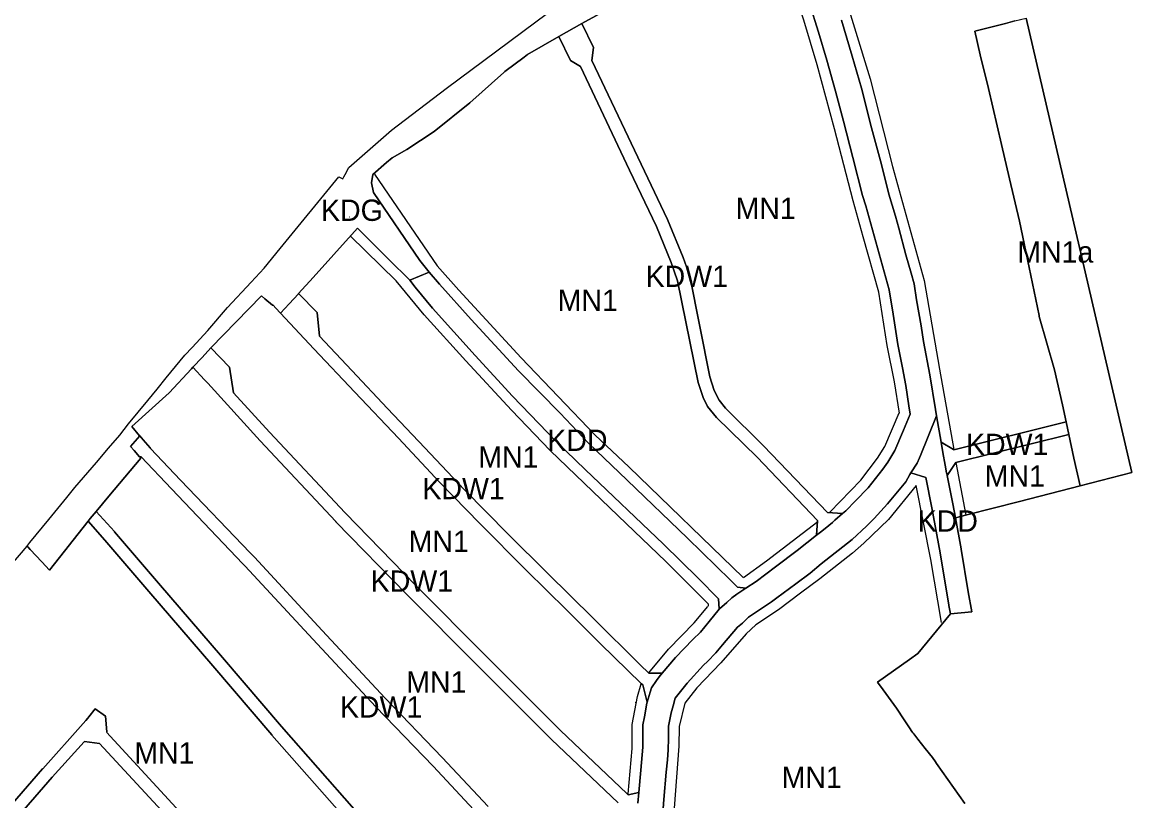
# Model space of a CAD drawing. Extents: x -284239 to -281592, y 34477 to 37267.
# Drawn here: x -283616 to -283093, y 35969 to 36334 of the extents above; entities that cross this region are included whole.
import ezdxf

# ---------------------------------------------------------------- set-up
doc = ezdxf.new("R2010")
doc.units = 0
for name, color, linetype in [('linie_rozgraniczajace', 7, 'Continuous'), ('linie_zabudowy_nieprzekraczalne', 7, 'Continuous'), ('oznaczenia_przeznaczen', 7, 'Continuous')]:
    doc.layers.add(name, color=color, linetype=linetype)

msp = doc.modelspace()

# ---------------------------------------------------------------- linework, layer by layer
at = {"layer": 'linie_rozgraniczajace'}
for points in [[(-283613.963, 36088.161), (-283613.66, 36088.52), (-283612.644, 36089.761), (-283603.69, 36100.7), (-283595.29, 36110.98), (-283591.49, 36115.62), (-283581.32, 36127.44), (-283575.7, 36134.13), (-283570.52, 36140.31), (-283566.39, 36145.49), (-283557.34, 36156.49), (-283552.95, 36161.85), (-283548.66, 36167.08), (-283539.89, 36177.82), (-283536.52, 36181.44), (-283529.1, 36189.39), (-283519.93, 36200.12), (-283508.754, 36212.115), (-283502.73, 36218.58), (-283495.149, 36227.855), (-283467.65, 36261.5), (-283466.676, 36261.042), (-283465.78, 36260.62), (-283465.27, 36261.48), (-283464.672, 36262.697), (-283463.07, 36265.96), (-283442.91, 36283.51), (-283417.32, 36302.99), (-283363.72, 36342.94)], [(-283246.84, 36343.001), (-283242.619, 36329.4), (-283238.711, 36316.321), (-283234.699, 36301.782), (-283230.895, 36287.661), (-283226.465, 36270.621), (-283221.984, 36252.696), (-283220.473, 36247.954), (-283209.478, 36208.403), (-283207.55, 36196.991), (-283205.361, 36182.818), (-283203.225, 36171.927), (-283201.661, 36163.485), (-283200.202, 36154.002), (-283199.552, 36150.099), (-283202.756, 36142.589), (-283206.82, 36133.002), (-283210.155, 36127.478), (-283212.396, 36124.195), (-283219.378, 36115.441), (-283225.215, 36109.396), (-283229.852, 36104.758), (-283231.322, 36103.46), (-283238.474, 36103.931), (-283268.495, 36135.283), (-283286.222, 36152.944), (-283289.265, 36156.648), (-283291.514, 36161.146), (-283293.631, 36167.628), (-283303.023, 36214.857), (-283306.198, 36223.72), (-283313.474, 36241.58), (-283348.995, 36316.183), (-283348.238, 36322.21), (-283353.632, 36333.486), (-283340.515, 36340.672)], [(-283207.55, 36196.991), (-283209.478, 36208.403), (-283220.473, 36247.954), (-283221.984, 36252.696), (-283226.465, 36270.621), (-283230.895, 36287.661), (-283234.699, 36301.782), (-283238.711, 36316.321), (-283242.619, 36329.4), (-283246.84, 36343.001)], [(-283340.515, 36340.672), (-283353.632, 36333.486), (-283364.544, 36327.384), (-283379.163, 36319.001), (-283380.781, 36317.801), (-283389.817, 36311.033), (-283390.333, 36310.51), (-283406.261, 36296.276), (-283423.036, 36282.89), (-283435.745, 36274.418), (-283442.674, 36270.514), (-283445.279, 36268.201), (-283451.741, 36262.623), (-283452.351, 36258.659), (-283451.504, 36254.253), (-283429.645, 36222.228), (-283425.239, 36216.805), (-283434.389, 36213.078), (-283436.183, 36214.833), (-283442.354, 36220.872), (-283458.959, 36237.478), (-283481.206, 36212.682), (-283483.36, 36210.282), (-283486.6, 36206.713), (-283486.665, 36206.641), (-283490.985, 36201.882), (-283494.997, 36197.453), (-283497.179, 36199.791), (-283498.58, 36201.281), (-283498.852, 36201.283), (-283502.383, 36204.239), (-283504.055, 36205.639), (-283527.673, 36181.245), (-283527.679, 36181.238)], [(-283231.833, 36335.08), (-283226.882, 36318.249), (-283222.453, 36303.19), (-283217.815, 36284.587), (-283213.594, 36269.006), (-283211.562, 36261.033), (-283209.582, 36253.425), (-283206.56, 36243.108), (-283204.944, 36237.428), (-283201.609, 36224.922), (-283199.212, 36216.272), (-283197.805, 36211.217), (-283196.659, 36203.818), (-283194.47, 36191.52), (-283193.376, 36184.172), (-283190.458, 36168.54), (-283187.696, 36152.23), (-283187.279, 36149.312), (-283194.803, 36130.699), (-283195.252, 36129.667), (-283196.398, 36127.061), (-283199.252, 36122.513), (-283199.733, 36121.746), (-283201.661, 36118.359), (-283210.207, 36107.937), (-283216.46, 36101.163), (-283220.108, 36097.515), (-283226.83, 36091.21), (-283241.316, 36079.746), (-283246.579, 36075.421), (-283253.249, 36070.419), (-283262.108, 36063.853), (-283264.609, 36061.977), (-283275.396, 36054.734), (-283278.314, 36052.024), (-283280.607, 36050.044), (-283287.641, 36041.759), (-283290.872, 36038.007), (-283294.728, 36033.942), (-283296.552, 36032.223), (-283304.264, 36023.781), (-283309.892, 36016.799), (-283310.882, 36013.099), (-283311.82, 36009.868), (-283313.07, 36003.615), (-283313.07, 35997.779), (-283313.227, 35992.411), (-283313.539, 35987.826), (-283314.113, 35981.938), (-283315.155, 35969.119), (-283316.458, 35952.079)], [(-283150.436, 36334.741), (-283154.879, 36333.612), (-283169.349, 36329.955), (-283166.705, 36318.833), (-283162.936, 36302.976), (-283156.734, 36276.738), (-283152.971, 36260.572), (-283148.359, 36240.695), (-283143.854, 36219.017), (-283139.137, 36196.384), (-283139.029, 36196.009), (-283131.834, 36170.915), (-283128.218, 36154.405), (-283126.492, 36146.51), (-283179.126, 36133.403), (-283179.331, 36133.563), (-283185.081, 36136.952), (-283187.279, 36149.312), (-283187.696, 36152.23), (-283190.458, 36168.54), (-283193.376, 36184.172), (-283194.47, 36191.52), (-283196.659, 36203.818), (-283197.805, 36211.217), (-283199.212, 36216.272), (-283201.609, 36224.922), (-283204.944, 36237.428), (-283206.56, 36243.108), (-283209.582, 36253.425), (-283211.562, 36261.033), (-283213.594, 36269.006), (-283217.815, 36284.587), (-283222.453, 36303.19), (-283226.882, 36318.249), (-283231.833, 36335.08)], [(-283173.975, 35967.24), (-283187.253, 35986.027), (-283187.803, 35986.836), (-283189.19, 35988.86), (-283192.547, 35993.138), (-283195.962, 35997.492), (-283197.93, 36000), (-283198.293, 36000.505), (-283198.766, 36001.163), (-283200, 36002.88), (-283202.432, 36006.641), (-283206.066, 36012.004), (-283212.292, 36020.669), (-283214.88, 36024.27), (-283199.925, 36034.933), (-283195.96, 36037.76), (-283180.69, 36056.377), (-283170.709, 36057.35), (-283172.447, 36066.68), (-283172.396, 36066.745), (-283175.668, 36086.704), (-283175.681, 36086.749), (-283175.687, 36086.809), (-283178.408, 36101.439), (-283172.953, 36102.779), (-283148.359, 36109.139), (-283119.79, 36116.401), (-283095.587, 36122.661), (-283145.114, 36336.093)], [(-283327.42, 35967.384), (-283326.952, 35972.467), (-283325.993, 35982.875), (-283325.108, 35993.662), (-283325.003, 36004.188), (-283324.326, 36007.992), (-283323.18, 36014.453), (-283323.073, 36014.805), (-283321.611, 36019.608), (-283320.991, 36021.644), (-283318.643, 36025.013), (-283317.396, 36026.803), (-283316.022, 36028.44), (-283309.788, 36035.87), (-283301.659, 36044.312), (-283298.063, 36047.803), (-283293.999, 36052.701), (-283289.232, 36058.583), (-283289.1, 36058.746), (-283285.654, 36061.727), (-283283.368, 36063.853), (-283280.969, 36065.555), (-283276.672, 36068.404), (-283271.904, 36071.565), (-283262.733, 36078.339), (-283252.624, 36086.051), (-283243.565, 36093.203), (-283241.733, 36094.649), (-283239.569, 36096.412), (-283236.106, 36099.235), (-283234.957, 36100.249), (-283231.322, 36103.46), (-283229.852, 36104.758), (-283225.215, 36109.396), (-283219.378, 36115.441), (-283212.396, 36124.195), (-283210.155, 36127.478), (-283206.82, 36133.002), (-283202.756, 36142.589), (-283199.552, 36150.099), (-283200.202, 36154.002), (-283201.661, 36163.485), (-283203.225, 36171.927), (-283205.361, 36182.818), (-283207.55, 36196.991)], [(-283527.679, 36181.238), (-283531.867, 36176.727), (-283536.178, 36172.086), (-283536.792, 36171.422), (-283547.242, 36160.125), (-283564.864, 36144.367), (-283561.188, 36139.938), (-283561.136, 36139.876), (-283565.373, 36134.962), (-283563.695, 36132.984), (-283561.208, 36130.053), (-283560.628, 36129.37), (-283575.54, 36111.578), (-283581.519, 36104.45), (-283584.351, 36101.073), (-283585.361, 36099.794), (-283603.498, 36076.841), (-283607.105, 36080.742), (-283612.5, 36086.577), (-283613.691, 36087.866), (-283613.963, 36088.161)], [(-283336.674, 35967.549), (-283367.894, 35997.315), (-283367.914, 35997.344), (-283367.946, 35997.365), (-283402.674, 36032.094), (-283435.824, 36065.377), (-283469.112, 36099.589), (-283469.139, 36099.622), (-283504.663, 36137.523), (-283529.151, 36164.573), (-283530.67, 36166.25), (-283536.178, 36172.086), (-283531.867, 36176.727), (-283527.679, 36181.238), (-283527.673, 36181.245), (-283519.066, 36172.18), (-283517.135, 36160.132), (-283500.301, 36141.643), (-283464.792, 36103.753), (-283431.552, 36069.589), (-283398.427, 36036.332), (-283363.728, 36001.633), (-283332.57, 35971.927), (-283331.992, 35971.417), (-283326.952, 35972.467), (-283327.42, 35967.384)], [(-283397.628, 35965.812), (-283419.135, 35988.903), (-283419.159, 35988.932), (-283445.93, 36016.761), (-283475.478, 36048.557), (-283507.302, 36082.891), (-283507.325, 36082.919), (-283509.297, 36084.981), (-283541.91, 36119.091), (-283556.017, 36133.906), (-283556.017, 36134.178), (-283556.172, 36134.27), (-283559.524, 36138.085), (-283561.135, 36139.918), (-283561.188, 36139.938), (-283564.864, 36144.367), (-283547.242, 36160.125), (-283536.792, 36171.422), (-283536.178, 36172.086), (-283530.67, 36166.25), (-283529.151, 36164.573), (-283504.663, 36137.523), (-283469.139, 36099.622), (-283469.112, 36099.589), (-283435.824, 36065.377), (-283402.674, 36032.094), (-283367.946, 35997.365), (-283367.914, 35997.344), (-283367.894, 35997.315), (-283336.674, 35967.549)], [(-283402.356, 35962.085), (-283423.5, 35984.79), (-283450.272, 36012.62), (-283450.297, 36012.651), (-283479.876, 36044.475), (-283511.678, 36078.789), (-283512.696, 36079.854), (-283546.263, 36114.963), (-283560.489, 36130.12), (-283561.208, 36130.053), (-283563.695, 36132.984), (-283565.373, 36134.962), (-283561.136, 36139.876), (-283561.188, 36139.938), (-283561.135, 36139.918), (-283559.524, 36138.085), (-283556.172, 36134.27), (-283556.017, 36134.178), (-283556.017, 36133.906), (-283541.91, 36119.091), (-283509.297, 36084.981), (-283507.325, 36082.919), (-283507.302, 36082.891), (-283475.478, 36048.557), (-283445.93, 36016.761), (-283419.159, 35988.932), (-283419.135, 35988.903), (-283397.628, 35965.812)], [(-283460.545, 35964.685), (-283494.569, 36003.366), (-283522.268, 36035.835), (-283552.336, 36070.789), (-283572.972, 36094.874), (-283572.999, 36094.894), (-283573.024, 36094.934), (-283581.519, 36104.45), (-283575.54, 36111.578), (-283560.628, 36129.37), (-283561.208, 36130.053), (-283560.489, 36130.12), (-283546.263, 36114.963), (-283512.696, 36079.854), (-283511.678, 36078.789), (-283479.876, 36044.475), (-283450.297, 36012.651), (-283450.272, 36012.62), (-283423.5, 35984.79), (-283402.356, 35962.085)], [(-283316.458, 35952.079), (-283315.155, 35969.119), (-283314.113, 35981.938), (-283313.539, 35987.826), (-283313.227, 35992.411), (-283313.07, 35997.779), (-283313.07, 36003.615), (-283311.82, 36009.868), (-283310.882, 36013.099), (-283309.892, 36016.799), (-283304.264, 36023.781), (-283296.552, 36032.223), (-283294.728, 36033.942), (-283290.872, 36038.007), (-283287.641, 36041.759), (-283280.607, 36050.044), (-283278.314, 36052.024), (-283275.396, 36054.734), (-283264.609, 36061.977), (-283262.108, 36063.853), (-283253.249, 36070.419), (-283246.579, 36075.421), (-283241.316, 36079.746), (-283226.83, 36091.21), (-283220.108, 36097.515), (-283216.46, 36101.163), (-283210.207, 36107.937), (-283201.661, 36118.359), (-283199.733, 36121.746), (-283199.252, 36122.513), (-283192.281, 36120.369), (-283192.261, 36120.287), (-283189.442, 36106.075), (-283185.528, 36085.033), (-283181.494, 36060.432), (-283181.473, 36060.357), (-283181.464, 36060.265), (-283180.69, 36056.377), (-283195.96, 36037.76), (-283199.925, 36034.933), (-283214.88, 36024.27), (-283212.292, 36020.669), (-283206.066, 36012.004), (-283202.432, 36006.641), (-283200, 36002.88), (-283198.766, 36001.163), (-283198.293, 36000.505), (-283197.93, 36000), (-283195.962, 35997.492), (-283192.547, 35993.138), (-283189.19, 35988.86), (-283187.803, 35986.836), (-283187.253, 35986.027), (-283173.975, 35967.24)], [(-283465.066, 35960.742), (-283499.091, 35999.424), (-283499.119, 35999.455), (-283526.824, 36031.931), (-283556.888, 36066.881), (-283577.502, 36090.94), (-283585.361, 36099.794), (-283584.351, 36101.073), (-283581.519, 36104.45), (-283573.024, 36094.934), (-283572.999, 36094.894), (-283572.972, 36094.874), (-283552.336, 36070.789), (-283522.268, 36035.835), (-283494.569, 36003.366), (-283460.545, 35964.685)], [(-283625.65, 36074.31), (-283613.963, 36088.161), (-283613.691, 36087.866), (-283612.5, 36086.577), (-283607.105, 36080.742), (-283603.498, 36076.841), (-283585.361, 36099.794), (-283577.502, 36090.94), (-283556.888, 36066.881), (-283526.824, 36031.931), (-283499.119, 35999.455), (-283499.091, 35999.424), (-283465.066, 35960.742)], [(-283540.379, 35961.4), (-283576.638, 36000.7), (-283576.568, 36000.86), (-283577.114, 36008.231), (-283582.059, 36011.652), (-283584.95, 36008.003), (-283585.504, 36007.304), (-283586.354, 36006.232), (-283587.63, 36004.808), (-283606.651, 35983.587), (-283606.677, 35983.554), (-283625.75, 35961.486)], [(-283625.75, 35961.486), (-283606.677, 35983.554), (-283606.651, 35983.587), (-283587.63, 36004.808), (-283586.354, 36006.232), (-283585.504, 36007.304), (-283584.95, 36008.003), (-283582.059, 36011.652), (-283577.114, 36008.231), (-283576.568, 36000.86), (-283576.638, 36000.7), (-283540.379, 35961.4)], [(-283621.534, 35957.2), (-283602.166, 35979.602), (-283587.205, 35996.293), (-283587.058, 35996.351), (-283580.055, 35995.51), (-283548.885, 35961.766)], [(-283548.885, 35961.766), (-283580.055, 35995.51), (-283587.058, 35996.351), (-283587.205, 35996.293), (-283602.166, 35979.602), (-283621.534, 35957.2)]]:
    msp.add_lwpolyline(points, dxfattribs=at)
for points in [[(-283364.544, 36327.384), (-283353.632, 36333.486), (-283348.238, 36322.21), (-283348.995, 36316.183), (-283313.474, 36241.58), (-283306.198, 36223.72), (-283303.023, 36214.857), (-283293.631, 36167.628), (-283291.514, 36161.146), (-283289.265, 36156.648), (-283286.222, 36152.944), (-283268.495, 36135.283), (-283238.474, 36103.931), (-283231.322, 36103.46), (-283234.957, 36100.249), (-283236.106, 36099.235), (-283239.569, 36096.412), (-283241.733, 36094.649), (-283243.565, 36093.203), (-283243.095, 36099.961), (-283243.116, 36100.138), (-283271.406, 36129.859), (-283290.456, 36148.512), (-283294.689, 36153.738), (-283296.673, 36157.971), (-283299.055, 36164.917), (-283308.712, 36212.674), (-283311.755, 36221.339), (-283318.634, 36238.206), (-283331.334, 36264.731), (-283354.372, 36313.367), (-283359.03, 36316.166)], [(-283169.349, 36329.955), (-283154.879, 36333.612), (-283150.436, 36334.741), (-283145.155, 36336.082), (-283145.114, 36336.093), (-283095.587, 36122.661), (-283119.79, 36116.401), (-283122.758, 36129.44), (-283125.189, 36140.555), (-283126.492, 36146.51), (-283128.218, 36154.405), (-283131.834, 36170.915), (-283139.029, 36196.009), (-283139.137, 36196.384), (-283143.854, 36219.017), (-283148.359, 36240.695), (-283152.971, 36260.572), (-283156.734, 36276.738), (-283162.936, 36302.976), (-283166.705, 36318.833)], [(-283452.351, 36258.659), (-283451.741, 36262.623), (-283445.279, 36268.201), (-283442.674, 36270.514), (-283435.745, 36274.418), (-283423.036, 36282.89), (-283406.261, 36296.276), (-283390.333, 36310.51), (-283389.817, 36311.033), (-283380.781, 36317.801), (-283379.163, 36319.001), (-283364.544, 36327.384), (-283359.03, 36316.166), (-283354.372, 36313.367), (-283331.334, 36264.731), (-283318.634, 36238.206), (-283311.755, 36221.339), (-283308.712, 36212.674), (-283299.055, 36164.917), (-283296.673, 36157.971), (-283294.689, 36153.738), (-283290.456, 36148.512), (-283271.406, 36129.859), (-283243.116, 36100.138), (-283243.095, 36099.961), (-283243.565, 36093.203), (-283252.624, 36086.051), (-283262.733, 36078.339), (-283271.904, 36071.565), (-283276.672, 36068.404), (-283280.709, 36068.859), (-283283.887, 36072.182), (-283304.042, 36091.801), (-283332.345, 36119.031), (-283350.57, 36136.399), (-283363.863, 36150.55), (-283383.375, 36170.49), (-283405.674, 36194.505), (-283420.463, 36211.063), (-283425.239, 36216.805), (-283429.645, 36222.228), (-283451.504, 36254.253)], [(-283486.6, 36206.713), (-283483.36, 36210.282), (-283481.206, 36212.682), (-283458.959, 36237.478), (-283442.354, 36220.872), (-283436.183, 36214.833), (-283434.389, 36213.078), (-283431.865, 36209.652), (-283423.685, 36199.865), (-283403.744, 36177.566), (-283386.162, 36158.591), (-283365.579, 36137.149), (-283352.071, 36124.07), (-283315.406, 36089.12), (-283299.11, 36073.039), (-283289.62, 36063.367), (-283289.246, 36058.643), (-283289.232, 36058.583), (-283293.999, 36052.701), (-283298.063, 36047.803), (-283301.659, 36044.312), (-283309.788, 36035.87), (-283316.022, 36028.44), (-283322.252, 36028.507), (-283326.293, 36032.417), (-283348.412, 36054.233), (-283369.752, 36075.356), (-283388.228, 36093.702), (-283408.96, 36114.738), (-283427.35, 36134.299), (-283444.786, 36152.818), (-283461.614, 36170.558), (-283476.714, 36186.678), (-283477.857, 36197.778)], [(-283434.389, 36213.078), (-283425.239, 36216.805), (-283420.463, 36211.063), (-283405.674, 36194.505), (-283383.375, 36170.49), (-283363.863, 36150.55), (-283350.57, 36136.399), (-283332.345, 36119.031), (-283304.042, 36091.801), (-283283.887, 36072.182), (-283280.709, 36068.859), (-283276.672, 36068.404), (-283280.969, 36065.555), (-283283.368, 36063.853), (-283285.654, 36061.727), (-283289.1, 36058.746), (-283289.232, 36058.583), (-283289.246, 36058.643), (-283289.62, 36063.367), (-283299.11, 36073.039), (-283315.406, 36089.12), (-283352.071, 36124.07), (-283365.579, 36137.149), (-283386.162, 36158.591), (-283403.744, 36177.566), (-283423.685, 36199.865), (-283431.865, 36209.652)], [(-283527.673, 36181.245), (-283504.055, 36205.639), (-283502.383, 36204.239), (-283498.852, 36201.283), (-283498.58, 36201.281), (-283497.179, 36199.791), (-283494.997, 36197.453), (-283479.483, 36180.837), (-283460.139, 36160.409), (-283439.754, 36138.766), (-283420.324, 36117.99), (-283401.587, 36098.777), (-283379.727, 36076.787), (-283360.643, 36058.007), (-283345.029, 36042.436), (-283325.685, 36023.526), (-283325.076, 36022.94), (-283323.073, 36014.805), (-283323.18, 36014.453), (-283324.326, 36007.992), (-283325.003, 36004.188), (-283325.108, 35993.662), (-283325.993, 35982.875), (-283326.952, 35972.467), (-283331.992, 35971.417), (-283332.57, 35971.927), (-283363.728, 36001.633), (-283398.427, 36036.332), (-283431.552, 36069.589), (-283464.792, 36103.753), (-283500.301, 36141.643), (-283517.135, 36160.132), (-283519.066, 36172.18)], [(-283494.997, 36197.453), (-283490.985, 36201.882), (-283486.665, 36206.641), (-283486.6, 36206.713), (-283477.857, 36197.778), (-283476.714, 36186.678), (-283461.614, 36170.558), (-283444.786, 36152.818), (-283427.35, 36134.299), (-283408.96, 36114.738), (-283388.228, 36093.702), (-283369.752, 36075.356), (-283348.412, 36054.233), (-283326.293, 36032.417), (-283322.252, 36028.507), (-283316.022, 36028.44), (-283317.396, 36026.803), (-283318.643, 36025.013), (-283320.991, 36021.644), (-283321.611, 36019.608), (-283323.073, 36014.805), (-283325.076, 36022.94), (-283325.685, 36023.526), (-283345.029, 36042.436), (-283360.643, 36058.007), (-283379.727, 36076.787), (-283401.587, 36098.777), (-283420.324, 36117.99), (-283439.754, 36138.766), (-283460.139, 36160.409), (-283479.483, 36180.837)], [(-283199.252, 36122.513), (-283196.398, 36127.061), (-283195.252, 36129.667), (-283194.803, 36130.699), (-283187.279, 36149.312), (-283185.081, 36136.952), (-283184.224, 36132.133), (-283183.17, 36126.204), (-283182.521, 36122.553), (-283182.509, 36122.458), (-283182.474, 36122.341), (-283182.273, 36121.329), (-283179.627, 36107.992), (-283179.624, 36107.961), (-283179.615, 36107.933), (-283178.408, 36101.439), (-283175.687, 36086.809), (-283175.681, 36086.749), (-283175.668, 36086.704), (-283172.396, 36066.745), (-283172.447, 36066.68), (-283170.709, 36057.35), (-283180.69, 36056.377), (-283181.464, 36060.265), (-283181.473, 36060.357), (-283181.494, 36060.432), (-283185.528, 36085.033), (-283189.442, 36106.075), (-283192.261, 36120.287), (-283192.281, 36120.369)], [(-283185.081, 36136.952), (-283179.331, 36133.563), (-283179.126, 36133.403), (-283126.492, 36146.51), (-283125.189, 36140.555), (-283178.163, 36127.443), (-283182.273, 36121.329), (-283182.474, 36122.341), (-283182.509, 36122.458), (-283182.521, 36122.553), (-283183.17, 36126.204), (-283184.224, 36132.133)], [(-283182.273, 36121.329), (-283178.163, 36127.443), (-283125.189, 36140.555), (-283122.758, 36129.44), (-283119.79, 36116.401), (-283148.359, 36109.139), (-283172.953, 36102.779), (-283178.408, 36101.439), (-283179.615, 36107.933), (-283179.624, 36107.961), (-283179.627, 36107.992)]]:
    msp.add_lwpolyline(points, close=True, dxfattribs=at)
at = {"layer": 'linie_zabudowy_nieprzekraczalne'}
for points in [[(-283097.207, 36475.404), (-283093.32, 36479.91), (-283103.894, 36468.034), (-283111.832, 36460.625), (-283125.325, 36448.521), (-283146.227, 36433.572), (-283155.885, 36429.272), (-283210.257, 36403.674), (-283240.948, 36386.343), (-283242.404, 36383.168), (-283241.345, 36381.184), (-283233.672, 36357.702), (-283218.459, 36307.63), (-283207.875, 36266.421), (-283193.059, 36212.909), (-283185.915, 36171.171), (-283179.178, 36133.437)], [(-283204.7, 36150.599), (-283206.949, 36165.284), (-283210.389, 36182.415), (-283214.358, 36207.419), (-283221.634, 36233.414), (-283226.396, 36250.215), (-283235.128, 36284.016), (-283243.197, 36314.178), (-283249.547, 36335.146), (-283262.517, 36374.989)], [(-283451.033, 36262.805), (-283421.532, 36219.744), (-283411.345, 36208.301), (-283382.109, 36176.551), (-283347.448, 36140.303), (-283331.573, 36125.354), (-283277.995, 36073.363)], [(-283462.537, 36242.674), (-283462.691, 36242.674)], [(-283294.267, 36059.869), (-283294.267, 36060.928), (-283314.243, 36080.97), (-283336.6, 36102.335), (-283368.483, 36132.961), (-283386.607, 36151.944), (-283408.17, 36175.096), (-283427.617, 36196.725), (-283440.846, 36212.733), (-283462.41, 36233.767)], [(-283237.386, 36104.069), (-283222.824, 36119.18), (-283214.887, 36129.366), (-283211.447, 36134.923), (-283204.833, 36150.665)], [(-283178.252, 36127.352), (-283173.48, 36102.643)], [(-283184.989, 36052.24), (-283189.884, 36081.873), (-283196.763, 36116.534), (-283209.86, 36100.659), (-283221.369, 36089.546), (-283226.661, 36084.784), (-283242.007, 36072.745), (-283251.003, 36065.998), (-283261.454, 36058.259), (-283272.037, 36051.116), (-283276.535, 36047.015), (-283288.441, 36033.388), (-283299.686, 36021.614), (-283305.375, 36014.405), (-283308.02, 36003.424), (-283308.153, 35994.164), (-283310.402, 35965.126), (-283313.189, 35927.062)], [(-283277.863, 36073.363), (-283267.01, 36081.278), (-283242.942, 36099.703)], [(-283322.185, 36028.662), (-283313.048, 36039.738), (-283301.009, 36052.174), (-283294.527, 36059.847)], [(-283331.975, 35971.777), (-283330.113, 35993.039), (-283330.113, 36004.417), (-283327.548, 36017.564), (-283325.757, 36023.503)], [(-283328.261, 36014.603), (-283328.313, 36014.827)]]:
    msp.add_lwpolyline(points, dxfattribs=at)

# ---------------------------------------------------------------- texts
at = {"layer": 'oznaczenia_przeznaczen'}
for s, p in [('KDG', (-283476.038, 36240.85)), ('MN1', (-283281.558, 36241.77)), ('MN1a', (-283149.354, 36221.258)), ('KDW1', (-283323.738, 36209.85)), ('MN1', (-283364.999, 36198.549)), ('KDD', (-283369.871, 36132.829)), ('KDW1', (-283173.405, 36130.914)), ('MN1', (-283402.238, 36125.002)), ('MN1', (-283164.617, 36116.066)), ('KDW1', (-283428.456, 36110.173)), ('KDD', (-283196.063, 36094.934)), ('MN1', (-283434.908, 36085.415)), ('KDW1', (-283452.721, 36066.691)), ('MN1', (-283436.092, 36019.34)), ('KDW1', (-283467.157, 36007.62)), ('MN1', (-283563.677, 35986.029)), ('MN1', (-283259.896, 35974.574))]:
    msp.add_text(s, height=10, dxfattribs=at).set_placement(p)

doc.saveas('drawing.dxf')
